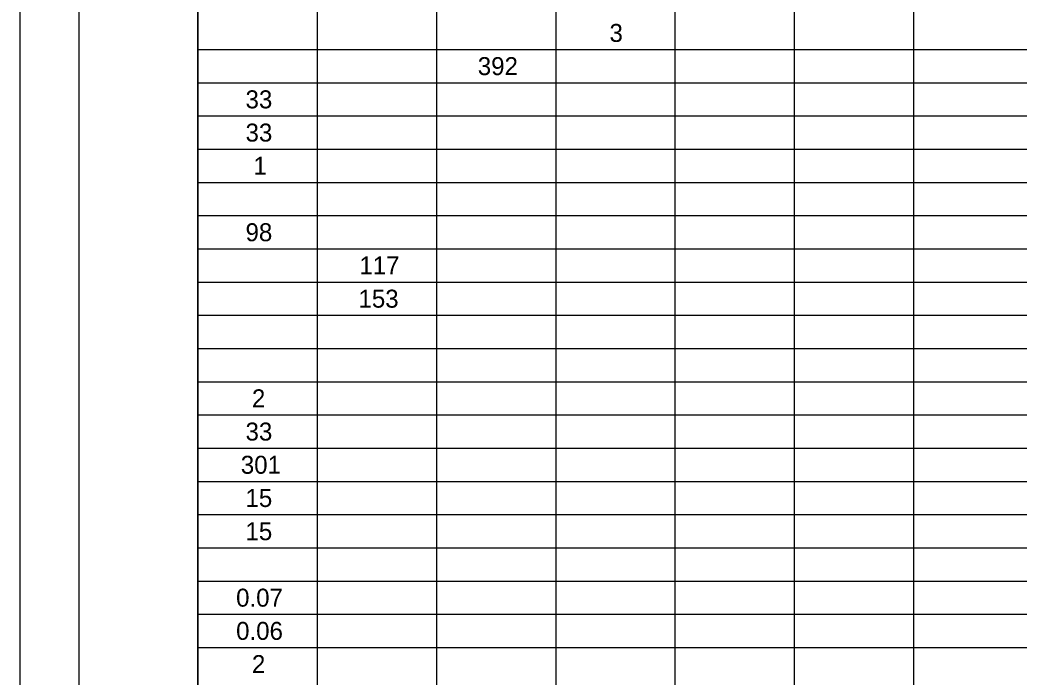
# Model space of a CAD drawing. Extents: x 0 to 34, y 0 to 22.
# Drawn here: x 0 to 8.42, y 10.89 to 16.43 of the extents above; entities that cross this region are included whole.
import ezdxf

# ---------------------------------------------------------------- set-up
doc = ezdxf.new("R2010")
doc.units = 0
for name, color, linetype in [('SH_Border', 7, 'Continuous'), ('SH_Cut_Line', 7, 'Continuous'), ('SH_Text', 7, 'Continuous')]:
    doc.layers.add(name, color=color, linetype=linetype)

msp = doc.modelspace()

# ---------------------------------------------------------------- linework, layer by layer
at = {"layer": 'SH_Border'}
for points in [[(0.5, 21.5), (1.5, 21.5), (1.5, 0.5), (0.5, 0.5)], [(1.5, 21.5), (33.5, 21.5), (33.5, 0.5), (1.5, 0.5)]]:
    msp.add_lwpolyline(points, close=True, dxfattribs=at)
at = {"layer": 'SH_Cut_Line'}
msp.add_lwpolyline([(0, 0), (34, 0), (34, 22), (0, 22)], close=True, dxfattribs=at)
at = {"layer": 'SH_Text'}
for p, q in [((1.5, 21.5), (1.5, 0.5016)), ((2.5046, 20.94), (2.5046, 0.5016)), ((3.5093, 20.94), (3.5093, 0.5016)), ((4.5139, 20.94), (4.5139, 0.5016)), ((5.5185, 20.94), (5.5185, 0.5016)), ((6.5231, 20.94), (6.5231, 0.5016)), ((7.5278, 20.94), (7.5278, 0.5016)), ((1.5, 16.1804), (32.0011, 16.1804)), ((1.5, 15.9004), (32.0011, 15.9004)), ((1.5, 15.6205), (32.0011, 15.6205)), ((1.5, 15.3405), (32.0011, 15.3405)), ((1.5, 15.0605), (32.0011, 15.0605)), ((1.5, 14.7805), (32.0011, 14.7805)), ((1.5, 14.5005), (32.0011, 14.5005)), ((1.5, 14.2206), (32.0011, 14.2206)), ((1.5, 13.9406), (32.0011, 13.9406)), ((1.5, 13.6606), (32.0011, 13.6606)), ((1.5, 13.3806), (32.0011, 13.3806)), ((1.5, 13.1007), (32.0011, 13.1007)), ((1.5, 12.8207), (32.0011, 12.8207)), ((1.5, 12.5407), (32.0011, 12.5407)), ((1.5, 12.2607), (32.0011, 12.2607)), ((1.5, 11.9807), (32.0011, 11.9807)), ((1.5, 11.7008), (32.0011, 11.7008)), ((1.5, 11.4208), (32.0011, 11.4208)), ((1.5, 11.1408), (32.0011, 11.1408))]:
    msp.add_line(p, q, dxfattribs=at)

# ---------------------------------------------------------------- texts
for s, height, p in [('3', 0.1515, (4.9676, 16.2446)), ('392', 0.15152, (3.8577, 15.9647)), ('33', 0.15152, (1.9007, 15.6847)), ('33', 0.15152, (1.9007, 15.4047)), ('1', 0.1515, (1.9669, 15.1247)), ('98', 0.15152, (1.9006, 14.5648)), ('117', 0.15152, (2.8595, 14.2848)), ('153', 0.15152, (2.8524, 14.0048)), ('2', 0.1515, (1.9544, 13.1649)), ('33', 0.15152, (1.9007, 12.8849)), ('301', 0.15152, (1.861, 12.6049)), ('15', 0.15152, (1.9002, 12.325)), ('15', 0.15152, (1.9002, 12.045)), ('0.07', 0.15152, (1.8213, 11.485)), ('0.06', 0.15152, (1.8213, 11.205)), ('2', 0.1515, (1.9544, 10.9251))]:
    msp.add_text(s, height=height, dxfattribs=at).set_placement(p)

doc.saveas('drawing.dxf')
